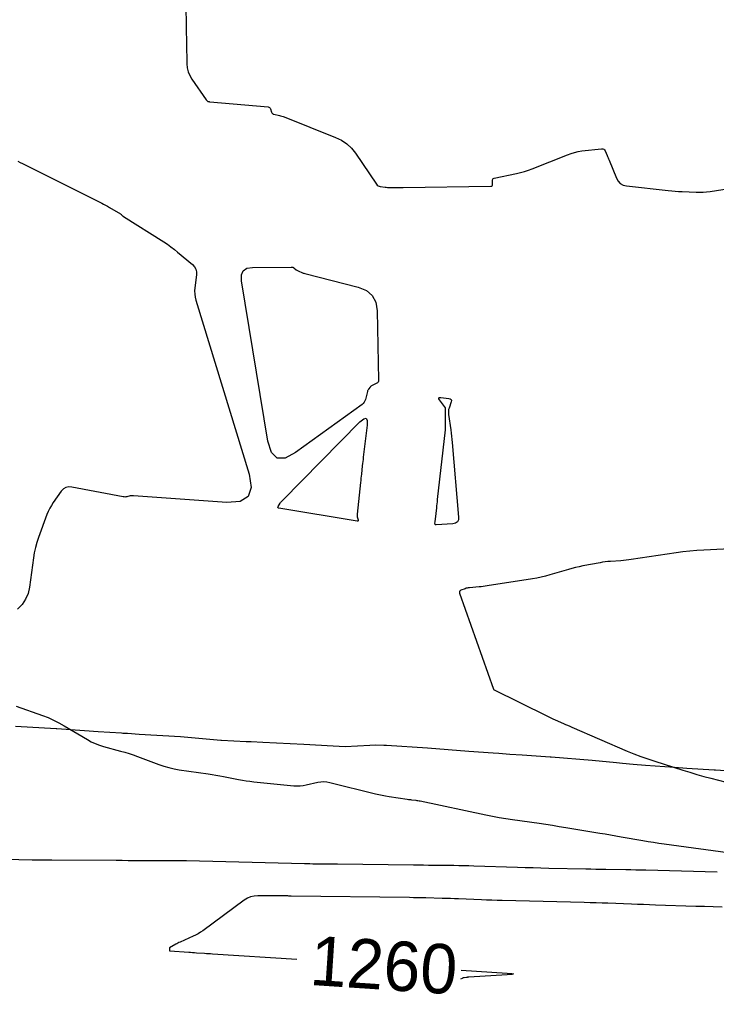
# Model space of a CAD drawing. Extents: x 658976 to 668721, y 639543 to 647196.
# Drawn here: x 660638.8 to 660723.4, y 642570.5 to 642688.9 of the extents above; entities that cross this region are included whole.
import ezdxf

# ---------------------------------------------------------------- set-up
doc = ezdxf.new("R2010")
doc.units = 0
for name, color, linetype in [('Ex_Contour Labels', 7, 'Continuous'), ('Ex_Major Contours', 7, 'Continuous'), ('Ex_Minor Contours', 7, 'Continuous'), ('R_Ramp 20 Degree Des Ls', 7, 'Continuous'), ('R_Ramp 20 Degree_Min Ls', 7, 'Continuous')]:
    doc.layers.add(name, color=color, linetype=linetype)

msp = doc.modelspace()

# ---------------------------------------------------------------- linework, layer by layer
at = {"layer": 'Ex_Major Contours'}
for points in [[(660658.95, 642692.28), (660659.01, 642688.37), (660659.02, 642687.78), (660659.03, 642687.19), (660659.04, 642686.6), (660659.06, 642686.01), (660659.11, 642683.51), (660659.15, 642683.01), (660659.27, 642682.52), (660659.46, 642682.06), (660659.72, 642681.62), (660661.46, 642679.11), (660661.48, 642679.09), (660661.49, 642679.07), (660661.51, 642679.05), (660661.53, 642679.04), (660661.6, 642678.97), (660661.61, 642678.96), (660661.63, 642678.95), (660661.66, 642678.94), (660661.68, 642678.93), (660661.78, 642678.91), (660661.81, 642678.91), (660661.83, 642678.9), (660661.86, 642678.9), (660661.88, 642678.9), (660668.97, 642678.27), (660669.07, 642678.25), (660669.15, 642678.2), (660669.21, 642678.13), (660669.25, 642678.04), (660669.39, 642677.62), (660669.43, 642677.53), (660669.49, 642677.45), (660669.57, 642677.4), (660669.67, 642677.37), (660670.35, 642677.22), (660670.49, 642677.18), (660670.64, 642677.14), (660670.78, 642677.1), (660670.93, 642677.04), (660677.17, 642674.56), (660677.88, 642674.22), (660678.52, 642673.78), (660679.09, 642673.26), (660679.58, 642672.64), (660682.15, 642668.88), (660682.24, 642668.77), (660682.35, 642668.69), (660682.47, 642668.63), (660682.6, 642668.6), (660683.18, 642668.52), (660683.32, 642668.5), (660683.47, 642668.49), (660683.61, 642668.48), (660683.76, 642668.48), (660684.6, 642668.46), (660684.79, 642668.46), (660684.98, 642668.46), (660685.17, 642668.46), (660685.36, 642668.46), (660696.04, 642668.62), (660696.14, 642668.63), (660696.21, 642668.68), (660696.25, 642668.75), (660696.25, 642668.85), (660696.22, 642669.32), (660696.23, 642669.42), (660696.26, 642669.5), (660696.33, 642669.56), (660696.43, 642669.6), (660699.15, 642670.17), (660699.63, 642670.28), (660700.12, 642670.42), (660700.59, 642670.57), (660701.06, 642670.75), (660705.36, 642672.46), (660705.78, 642672.62), (660706.21, 642672.74), (660706.65, 642672.84), (660707.1, 642672.91), (660709.49, 642673.19), (660709.63, 642673.19), (660709.75, 642673.14), (660709.84, 642673.06), (660709.92, 642672.94), (660710.15, 642672.37), (660710.21, 642672.23), (660710.27, 642672.08), (660710.33, 642671.94), (660710.39, 642671.8), (660711.29, 642669.6), (660711.49, 642669.23), (660711.76, 642668.95), (660712.1, 642668.77), (660712.51, 642668.67), (660717.57, 642668.11), (660718, 642668.07), (660718.42, 642668.04), (660718.85, 642668.01), (660719.27, 642667.99), (660720.98, 642667.92), (660721.4, 642667.91), (660721.83, 642667.92), (660722.25, 642667.96), (660722.67, 642668.01), (660727.07, 642668.66)], [(660725.87, 642624.62), (660721.91, 642624.45), (660721.06, 642624.4), (660720.21, 642624.33), (660719.37, 642624.24), (660718.53, 642624.12), (660713.09, 642623.28), (660712.78, 642623.24), (660712.46, 642623.2), (660712.14, 642623.17), (660711.83, 642623.14), (660710.56, 642623.06), (660710.24, 642623.04), (660709.93, 642623.01), (660709.61, 642622.96), (660709.3, 642622.91), (660707.22, 642622.51), (660706.78, 642622.42), (660706.33, 642622.32), (660705.89, 642622.21), (660705.45, 642622.08), (660703.21, 642621.42), (660702.69, 642621.27), (660702.16, 642621.14), (660701.63, 642621.03), (660701.1, 642620.94), (660695.58, 642620.08), (660695.34, 642620.05), (660695.09, 642620.02), (660694.85, 642619.99), (660694.61, 642619.97), (660693.42, 642619.87), (660693.29, 642619.85), (660693.16, 642619.83), (660693.03, 642619.8), (660692.91, 642619.75), (660692.4, 642619.57), (660692.3, 642619.51), (660692.24, 642619.44), (660692.22, 642619.34), (660692.24, 642619.22), (660696.34, 642607.55), (660696.34, 642607.54), (660696.35, 642607.51), (660696.35, 642607.5), (660702.82, 642604.3), (660703.07, 642604.18), (660703.32, 642604.06), (660703.57, 642603.94), (660703.83, 642603.83), (660704.85, 642603.39), (660705.1, 642603.27), (660705.36, 642603.16), (660705.61, 642603.05), (660705.87, 642602.94), (660712.6, 642600.04), (660713.42, 642599.7), (660714.25, 642599.38), (660715.09, 642599.08), (660715.94, 642598.8), (660719.34, 642597.72), (660720.19, 642597.45), (660721.04, 642597.2), (660721.9, 642596.96), (660722.77, 642596.73), (660726.47, 642595.77)], [(660724.12, 642581.06), (660723.06, 642581.1), (660722, 642581.14), (660720.94, 642581.17), (660716.02, 642581.33), (660715.3, 642581.36), (660714.58, 642581.38), (660713.86, 642581.41), (660713.14, 642581.43), (660710.26, 642581.54), (660709.54, 642581.56), (660708.82, 642581.59), (660708.1, 642581.61), (660707.38, 642581.63), (660697.41, 642581.88), (660696.78, 642581.89), (660696.15, 642581.91), (660695.52, 642581.93), (660694.89, 642581.96), (660692.1, 642582.08), (660691.6, 642582.1), (660691.11, 642582.11), (660690.61, 642582.13), (660690.12, 642582.14), (660688.13, 642582.19), (660687.64, 642582.2), (660687.14, 642582.21), (660686.65, 642582.22), (660686.15, 642582.23), (660671.77, 642582.43), (660671.64, 642582.43), (660671.5, 642582.43), (660671.37, 642582.44), (660671.24, 642582.44), (660670.72, 642582.46), (660670.58, 642582.46), (660670.45, 642582.46), (660670.32, 642582.46), (660670.19, 642582.46), (660667.72, 642582.46), (660667.27, 642582.43), (660666.85, 642582.33), (660666.45, 642582.16), (660666.07, 642581.92), (660661.02, 642578.22), (660660.74, 642578.03), (660660.46, 642577.85), (660660.16, 642577.69), (660659.86, 642577.55), (660658.27, 642576.84), (660658.14, 642576.78), (660658.01, 642576.71), (660657.88, 642576.64), (660657.75, 642576.57), (660657.01, 642576.12), (660657.01, 642576.12), (660657, 642576.11), (660657, 642576.1), (660657, 642576.09), (660656.98, 642575.83), (660656.99, 642575.8), (660657, 642575.78), (660657.02, 642575.77), (660657.05, 642575.76), (660659.32, 642575.61), (660659.56, 642575.59), (660659.8, 642575.58), (660660.04, 642575.56), (660660.28, 642575.54), (660661.24, 642575.48), (660661.48, 642575.46), (660661.72, 642575.45), (660661.96, 642575.43), (660662.2, 642575.41), (660672.46, 642574.74)], [(660692.42, 642573.43), (660698, 642573.06), (660698.6, 642573.01), (660698.8, 642572.96), (660698.6, 642572.91), (660698, 642572.86), (660693.35, 642572.57), (660693.28, 642572.57), (660693.21, 642572.56), (660693.14, 642572.55), (660693.07, 642572.54), (660692.79, 642572.51), (660692.73, 642572.5), (660692.66, 642572.48), (660692.59, 642572.46), (660692.53, 642572.43), (660692.35, 642572.35)]]:
    msp.add_lwpolyline(points, dxfattribs=at)
at = {"layer": 'Ex_Minor Contours'}
for points in [[(660638.58, 642671.67), (660638.85, 642671.52), (660639.12, 642671.38), (660648.75, 642666.57), (660648.99, 642666.44), (660649.23, 642666.32), (660649.46, 642666.19), (660649.7, 642666.05), (660651.03, 642665.27), (660651.07, 642665.25), (660651.1, 642665.23), (660651.13, 642665.2), (660651.16, 642665.17), (660651.28, 642665.05), (660651.31, 642665.02), (660651.34, 642665), (660651.37, 642664.97), (660651.41, 642664.95), (660656.31, 642661.86), (660656.74, 642661.58), (660657.16, 642661.28), (660657.58, 642660.96), (660657.98, 642660.63), (660659.77, 642659.13), (660660.02, 642658.86), (660660.19, 642658.55), (660660.27, 642658.22), (660660.27, 642657.85), (660660.07, 642656.3), (660660.04, 642655.91), (660660.05, 642655.53), (660660.1, 642655.15), (660660.2, 642654.78), (660666.67, 642633.65), (660666.92, 642632.05), (660666.55, 642630.95), (660665.56, 642630.35), (660663.95, 642630.24), (660652.61, 642631.05), (660652.51, 642631.05), (660652.4, 642631.05), (660652.3, 642631.04), (660652.2, 642631.01), (660651.79, 642630.91), (660651.68, 642630.89), (660651.58, 642630.88), (660651.48, 642630.89), (660651.37, 642630.9), (660645.14, 642632.1), (660644.76, 642632.13), (660644.41, 642632.05), (660644.1, 642631.87), (660643.84, 642631.58), (660642.87, 642630.22), (660642.64, 642629.87), (660642.44, 642629.52), (660642.26, 642629.14), (660642.1, 642628.76), (660641.07, 642625.95), (660640.87, 642625.35), (660640.7, 642624.74), (660640.56, 642624.12), (660640.46, 642623.49), (660639.97, 642619.94), (660639.8, 642619.18), (660639.5, 642618.47), (660639.08, 642617.84), (660638.53, 642617.28)], [(660638.36, 642605.48), (660641.55, 642604.35), (660642.23, 642604.09), (660642.9, 642603.8), (660643.55, 642603.47), (660644.18, 642603.11), (660647.02, 642601.42), (660647.49, 642601.17), (660647.97, 642600.94), (660648.47, 642600.75), (660648.98, 642600.6), (660651.05, 642600.04), (660651.57, 642599.9), (660652.08, 642599.74), (660652.59, 642599.57), (660653.09, 642599.39), (660655.7, 642598.41), (660656.3, 642598.2), (660656.92, 642598.03), (660657.54, 642597.88), (660658.17, 642597.77), (660661.7, 642597.26), (660662.17, 642597.19), (660662.63, 642597.12), (660663.09, 642597.03), (660663.55, 642596.95), (660665.38, 642596.58), (660665.84, 642596.49), (660666.3, 642596.42), (660666.76, 642596.36), (660667.23, 642596.31), (660672.11, 642595.83), (660672.48, 642595.81), (660672.85, 642595.82), (660673.22, 642595.86), (660673.58, 642595.92), (660675.03, 642596.24), (660675.39, 642596.3), (660675.75, 642596.32), (660676.12, 642596.29), (660676.48, 642596.22), (660682.02, 642594.84), (660682.42, 642594.75), (660682.83, 642594.66), (660683.24, 642594.58), (660683.66, 642594.52), (660685.88, 642594.18), (660686.01, 642594.17), (660686.14, 642594.15), (660686.27, 642594.13), (660686.4, 642594.11), (660686.92, 642594.05), (660687.05, 642594.03), (660687.18, 642594.02), (660687.31, 642593.99), (660687.43, 642593.97), (660695.43, 642592.29), (660696.23, 642592.13), (660697.04, 642591.98), (660697.84, 642591.85), (660698.65, 642591.73), (660701.9, 642591.26), (660702.71, 642591.14), (660703.52, 642591.02), (660704.32, 642590.89), (660705.13, 642590.76), (660709.27, 642590.07), (660709.92, 642589.97), (660710.57, 642589.85), (660711.23, 642589.74), (660711.88, 642589.63), (660714.49, 642589.16), (660715.14, 642589.05), (660715.79, 642588.95), (660716.45, 642588.85), (660717.1, 642588.76), (660725.73, 642587.6)], [(660723.51, 642585.34), (660714.85, 642585.55), (660714.25, 642585.57), (660713.64, 642585.58), (660713.04, 642585.59), (660712.43, 642585.6), (660710, 642585.64), (660709.4, 642585.65), (660708.79, 642585.66), (660708.19, 642585.67), (660707.58, 642585.68), (660703.07, 642585.79), (660702.12, 642585.81), (660701.17, 642585.84), (660700.22, 642585.86), (660699.26, 642585.89), (660693.98, 642586.07), (660693.37, 642586.09), (660692.76, 642586.1), (660692.15, 642586.11), (660691.53, 642586.12), (660689.08, 642586.14), (660688.47, 642586.15), (660687.86, 642586.16), (660687.25, 642586.16), (660686.63, 642586.17), (660677.39, 642586.28), (660677.06, 642586.28), (660676.72, 642586.29), (660676.39, 642586.29), (660676.06, 642586.29), (660674.72, 642586.31), (660674.39, 642586.31), (660674.05, 642586.32), (660673.72, 642586.32), (660673.39, 642586.33), (660659.07, 642586.69), (660658.94, 642586.69), (660658.8, 642586.69), (660658.67, 642586.7), (660658.53, 642586.7), (660658, 642586.71), (660657.86, 642586.71), (660657.73, 642586.71), (660657.59, 642586.71), (660657.46, 642586.71), (660653.4, 642586.72), (660652.68, 642586.72), (660651.95, 642586.72), (660651.23, 642586.73), (660650.51, 642586.73), (660642.68, 642586.77), (660642.48, 642586.77), (660642.28, 642586.77), (660642.09, 642586.78), (660641.89, 642586.78), (660641.1, 642586.78), (660640.9, 642586.78), (660640.7, 642586.79), (660640.5, 642586.79), (660640.3, 642586.79), (660632.12, 642586.98)]]:
    msp.add_lwpolyline(points, dxfattribs=at)
for points in [[(660680.73, 642642.56), (660680.64, 642642.4), (660680.53, 642642.26), (660680.38, 642642.14), (660672.3, 642636.29), (660671.05, 642635.62), (660670.07, 642635.62), (660669.37, 642636.31), (660668.95, 642637.67), (660665.73, 642657.14), (660665.72, 642657.85), (660665.94, 642658.35), (660666.4, 642658.66), (660667.09, 642658.77), (660671.79, 642658.82), (660671.88, 642658.82), (660671.96, 642658.8), (660672.04, 642658.76), (660672.11, 642658.71), (660672.38, 642658.49), (660672.45, 642658.44), (660672.53, 642658.39), (660672.61, 642658.35), (660672.69, 642658.31), (660673.06, 642658.16), (660673.15, 642658.13), (660673.24, 642658.09), (660673.33, 642658.06), (660673.42, 642658.04), (660679.93, 642656.38), (660680.91, 642655.98), (660681.61, 642655.38), (660682.05, 642654.55), (660682.21, 642653.51), (660682.38, 642645.07), (660682.37, 642644.95), (660682.33, 642644.85), (660682.26, 642644.77), (660682.16, 642644.7), (660681.62, 642644.44), (660681.55, 642644.4), (660681.49, 642644.35), (660681.43, 642644.3), (660681.37, 642644.23), (660681.18, 642643.98), (660681.13, 642643.91), (660681.09, 642643.84), (660681.06, 642643.77), (660681.04, 642643.69), (660680.79, 642642.74)], [(660690.52, 642641.71), (660690.52, 642641.71), (660690.52, 642641.72), (660689.79, 642642.68), (660689.71, 642642.82), (660689.71, 642642.92), (660689.79, 642642.97), (660689.95, 642642.97), (660690.94, 642642.87), (660691.1, 642642.83), (660691.2, 642642.74), (660691.24, 642642.62), (660691.21, 642642.45), (660690.96, 642641.69), (660690.9, 642641.5), (660690.88, 642641.31), (660690.87, 642641.11), (660690.89, 642640.92), (660691.16, 642639.03), (660691.21, 642638.65), (660691.26, 642638.27), (660691.3, 642637.89), (660691.34, 642637.5), (660692.1, 642628.42), (660692.09, 642628.1), (660691.97, 642627.86), (660691.75, 642627.71), (660691.43, 642627.64), (660689.37, 642627.52), (660689.31, 642627.52), (660689.27, 642627.55), (660689.25, 642627.59), (660689.24, 642627.65), (660689.27, 642627.91), (660689.27, 642627.98), (660689.28, 642628.05), (660689.29, 642628.11), (660689.29, 642628.18), (660689.45, 642629.56), (660689.48, 642629.82), (660689.51, 642630.07), (660689.54, 642630.32), (660689.57, 642630.57), (660690.52, 642639.04), (660690.53, 642639.07), (660690.53, 642639.13), (660690.53, 642639.14), (660690.54, 642639.16), (660690.54, 642639.17), (660690.54, 642639.18), (660690.54, 642641.67), (660690.54, 642641.68), (660690.54, 642641.69), (660690.54, 642641.7), (660690.53, 642641.7)], [(660679.92, 642628.03), (660679.9, 642627.98), (660679.86, 642627.95), (660679.78, 642627.96), (660670.29, 642629.52), (660670.2, 642629.55), (660670.15, 642629.6), (660670.15, 642629.66), (660670.19, 642629.75), (660670.42, 642630.12), (660670.48, 642630.22), (660670.55, 642630.3), (660670.62, 642630.39), (660670.7, 642630.47), (660680.13, 642640.03), (660680.58, 642640.39), (660680.87, 642640.45), (660681.01, 642640.19), (660681, 642639.61), (660680.53, 642635.71), (660680.5, 642635.46), (660680.47, 642635.2), (660680.44, 642634.95), (660680.41, 642634.69), (660680.31, 642633.68), (660680.28, 642633.42), (660680.25, 642633.17), (660680.23, 642632.91), (660680.2, 642632.66), (660679.78, 642628.82), (660679.78, 642628.73), (660679.78, 642628.64), (660679.79, 642628.55), (660679.81, 642628.46), (660679.91, 642628.1)]]:
    msp.add_lwpolyline(points, close=True, dxfattribs=at)
at = {"layer": 'R_Ramp 20 Degree Des Ls'}
msp.add_lwpolyline([(660638.3, 642603.06), (660643.24, 642602.77), (660643.31, 642602.77), (660644.44, 642602.69), (660648.31, 642602.41), (660651.14, 642602.23), (660651.33, 642602.22), (660651.9, 642602.19), (660653.31, 642602.1), (660658.31, 642601.79), (660663.22, 642601.35), (660663.31, 642601.35), (660666.31, 642601.2), (660666.92, 642601.18), (660668.31, 642601.13), (660673.32, 642600.87), (660676.89, 642600.67), (660678.32, 642600.6), (660681.33, 642600.74), (660681.98, 642600.77), (660683.01, 642600.75), (660683.24, 642600.74), (660683.35, 642600.73), (660688.35, 642600.42), (660693.35, 642600.04), (660696.32, 642599.82), (660697, 642599.77), (660698.35, 642599.67), (660699.84, 642599.56), (660703.22, 642599.33), (660703.35, 642599.33), (660708.35, 642598.91), (660711.29, 642598.64), (660712.01, 642598.58), (660713.34, 642598.46), (660714.83, 642598.34), (660718.34, 642598.09), (660719.85, 642597.97), (660723.18, 642597.76), (660723.34, 642597.75), (660726.27, 642597.56)], dxfattribs=at)
at = {"layer": 'R_Ramp 20 Degree_Min Ls'}
msp.add_lwpolyline([(660638.3, 642603.06), (660643.24, 642602.77), (660643.31, 642602.77), (660644.44, 642602.69), (660648.31, 642602.41), (660651.14, 642602.23), (660651.33, 642602.22), (660651.9, 642602.19), (660653.31, 642602.1), (660658.31, 642601.79), (660663.22, 642601.35), (660663.31, 642601.35), (660666.31, 642601.2), (660666.92, 642601.18), (660668.31, 642601.13), (660673.32, 642600.87), (660676.89, 642600.67), (660678.32, 642600.6), (660681.33, 642600.74), (660681.98, 642600.77), (660683.01, 642600.75), (660683.24, 642600.74), (660683.35, 642600.73), (660688.35, 642600.42), (660693.35, 642600.04), (660696.32, 642599.82), (660697, 642599.77), (660698.35, 642599.67), (660699.84, 642599.56), (660703.22, 642599.33), (660703.35, 642599.33), (660708.35, 642598.91), (660711.29, 642598.64), (660712.01, 642598.58), (660713.34, 642598.46), (660714.83, 642598.34), (660718.34, 642598.09), (660719.85, 642597.97), (660723.18, 642597.76), (660723.34, 642597.75), (660726.27, 642597.56)], dxfattribs=at)

# ---------------------------------------------------------------- texts
at = {"layer": 'Ex_Contour Labels'}
msp.add_text('1260', height=6, rotation=356.2415, dxfattribs=at).set_placement((660673.93, 642571.64))

doc.saveas('drawing.dxf')
